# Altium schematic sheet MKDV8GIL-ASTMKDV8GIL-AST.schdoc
size 127 x 101 mm
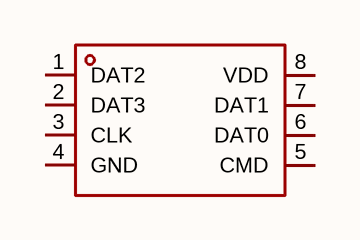
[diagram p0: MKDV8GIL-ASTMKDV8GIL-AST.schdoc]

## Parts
U?  mkdv8gil-ast  [LGA-8_L6.0-W8.0-P1.27-TL]  (value not drawn)

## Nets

Not connected (* = marked no-connect by the designer): U? 1(DAT2) 2(DAT3) 3(CLK) 4(GND) 5(CMD) 6(DAT0) 7(DAT1) 8(VDD)

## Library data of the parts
U? = mkdv8gil-ast: 存储容量:8Gbit;时钟频率(fc):50MHz;工作电压:2.7V~3.6V;; Manufacturer: MK(米客方德); AddInBom: yes; ModelId: 1f88d973af574684b0007f41a35ee8d9; ModelName: LGA-8_L6.0-W8.0-H0.8-P1.27; ModelTransform: 314.96,236.22,0,0,0,0,0,0.005,0; Memory Size: 8Gbit; Clock Frequency: 50MHz; Data Retention - TDR (Year): 10年; Standby Supply Current: 130uA; Program / Erase Cycles: 10万次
